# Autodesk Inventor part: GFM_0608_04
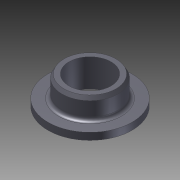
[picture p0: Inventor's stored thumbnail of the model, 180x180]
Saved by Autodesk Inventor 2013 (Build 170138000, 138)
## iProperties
Created: 2012-07
Part Number: GFM_0608_04
Material: PC/ABS-Kunststoff
Document SubType Name: Modeling
Designer: rYan
Mass: 0.224566 g
Surface Area: 3.47286 cm^2
Volume: 0.150412 cm^3
Density: 1.493 g/cm^3
Übersetzungsnorm: STEP AP214IS
Dateiname: GFM_0608_04_1.stp
Vorprozessor: ACIS
Postprozessor: Build: 138, Release: 2013 RTM - Date: Thu 03/01/2012
Gesendete Einheiten: Millimeter
Unbestimmtheit: 1e-06
Author: rYan
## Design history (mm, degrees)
node "11"
node "1"
node "Basis1"
